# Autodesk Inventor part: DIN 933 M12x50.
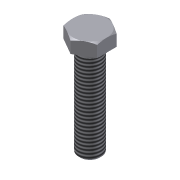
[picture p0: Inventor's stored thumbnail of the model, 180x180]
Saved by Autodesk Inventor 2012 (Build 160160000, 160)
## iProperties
Created: 2001-01
Part Number: DIN 933 M12x50.
Material: Steel, Mild
Document SubType Name: Modeling
Description: Sechskantschraube DIN 933 - M12x50.
Standard: DIN 933
Density: 7.86 g/cm^3
+MSCProtocol1+ProtocolID: P00040920144516246
+MSCProtocol2+Protocol: P00040920144516246<@PID>[Acad]<@EL>CBFVarsChanged=1<@EL>SmartPart=1<@EL>Update=0<@EL>ReallySmartPart=1<@EL>Loop=0<@EL>Optim=0<@EL>[View]<@EL>View=MODEL<@EL>Desc
Company: CAD-Verlag
Control State: 0
Master: False
Checked Out: False
Shininess: 20.0
Length Units: 11269
Angle Units: 11279
Time Units: 11290
Mass Units: 11283
Length Display Precision: 3
Angle Display Precision: 2
BOM1: Sechskantschraube
BOM2: M12x50
BOM3: DIN 933
Density: 7.859999999999999
Volumn: 5.59798751986722
Area: 24.439342304675858
PropertySet Name: Model Information
Author: Jürgen Kronas
Revision Number: 1
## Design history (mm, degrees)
node "WorkPlane1"
node "Sketch1"
node "WorkPoint1"
extrude "ExtrusionBlind1" new body distance "d2" = 50 (= prf_l); taper "d3" = 0 deg
  node "Sketch2" dims "d1" = 12 (= prf_d)
chamfer "Chamfer1" distance "d4" = 0.875 (= msp_z); stored, may be unused: second distance "d5" = 0.875 (= msp_z), angle "d31" = 45 deg
node "WorkAxis1"
sketch "Sketch3" dims "d8" = 17 (= prf_dw)
  geometry: C1 r 6 at (0, 0) reference
  constraints: 1 other
extrude "ExtrusionBlind2" join sketch "Sketch3" distance "d9" = 0.6 (= prf_c); taper "d10" = 0 deg
sketch "Sketch4" dims "d13" = 18 (= prf_s)
  geometry: L1 (-9, 5.196)-(-9, -5.196); L2 (0, 10.392)-(-9, 5.196); L3 (9, 5.196)-(0, 10.392); L4 (9, -5.196)-(9, 5.196); L5 (0, -10.392)-(9, -5.196); L6 (-9, -5.196)-(0, -10.392); C1 r 8.5 at (0, 0) reference; C2 r 6 at (0, 0) reference; C3 r 5.125 at (0, 0) reference
  constraints: 12 end point, 4 vertical, 2 parallel, 7 other
extrude "ExtrusionBlind3" join sketch "Sketch4" distance "d14" = 6.9 (= -prf_c + prf_k); taper "d15" = 0 deg
sketch "Sketch5"
  geometry: L1 (-10.392, 6.696)-(-9, 7.5); L2 (0, -50.981)-(0, 0.981); L3 (0, -62.677)-(0, 19.196) reference; L4 (-9, 7.5)-(-10.392, 7.5); L5 (-10.392, 7.5)-(-10.392, 6.696); L6 (-10.392, 0.6)-(-10.392, 7.5) reference
  constraints: 8 end point, 2 perpendicular
  dimensions: "d20" = 0 distance between parallel lines of L6 L5; "d21" = 0 distance from line of L6.end L4; "d22" = 9 distance from line of L3 L1.end (= 0.5 x prf_s); "d23" = 60 deg angle of L6 L1
revolve "RevolutionFull1" sketch "Sketch5" stored, may be unused: angle "d18" = 360 deg
fillet "Fillet1" dims "d19" = 0.6 (= prf_r)
feature "Ms_Thread" dims "d25" = 0, "prf_b" = 46.5
node "MSC_A1"
node "MSC_PF1"
node "MSC_PT1"
node "Volumenkörper1"
node "Volumenkörpern"
node "Oberflächenkörpern"
other parameters: "prf_p" = 1.75 [user parameter; used in 1 equation term], "prf_l" = 50 [user parameter; used in 1 equation term], "prf_k" = 7.5 [user parameter; used in 1 equation term], "prf_d" = 12 [user parameter; used in 1 equation term], "prf_s" = 18 [user parameter; used in 2 equation terms], "prf_r" = 0.6 [user parameter; used in 1 equation term], "prf_dw" = 17 [user parameter; used in 1 equation term], "prf_c" = 0.6 [user parameter; used in 2 equation terms], "msp_z" = 0.875 (= 0.5 x prf_p) [user parameter; used in 2 equation terms], "d6" = 0, "d7" = 15 (derived), "d11" = 0, "d12" = 17 (derived), "d16" = 30 deg (derived), "d28" = 0, "d29" = 0, "d30" = 0
